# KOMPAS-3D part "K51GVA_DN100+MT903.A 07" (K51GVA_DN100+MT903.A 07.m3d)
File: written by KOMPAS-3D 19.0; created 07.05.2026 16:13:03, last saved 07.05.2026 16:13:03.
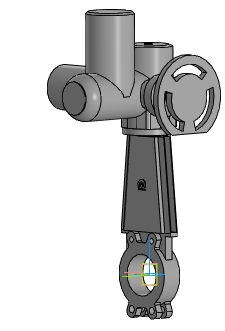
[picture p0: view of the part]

Document properties: Автор: Энергия; Полное имя файла: ..\K51GVA_DN50-DN1000+MT903.A\K51GVA_DN100+MT903.A 07.a3d

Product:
- Part/product: K51GVA_DN100+MT903.A 07
    Масса: 75.4732

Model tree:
1. Операция без истории:1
